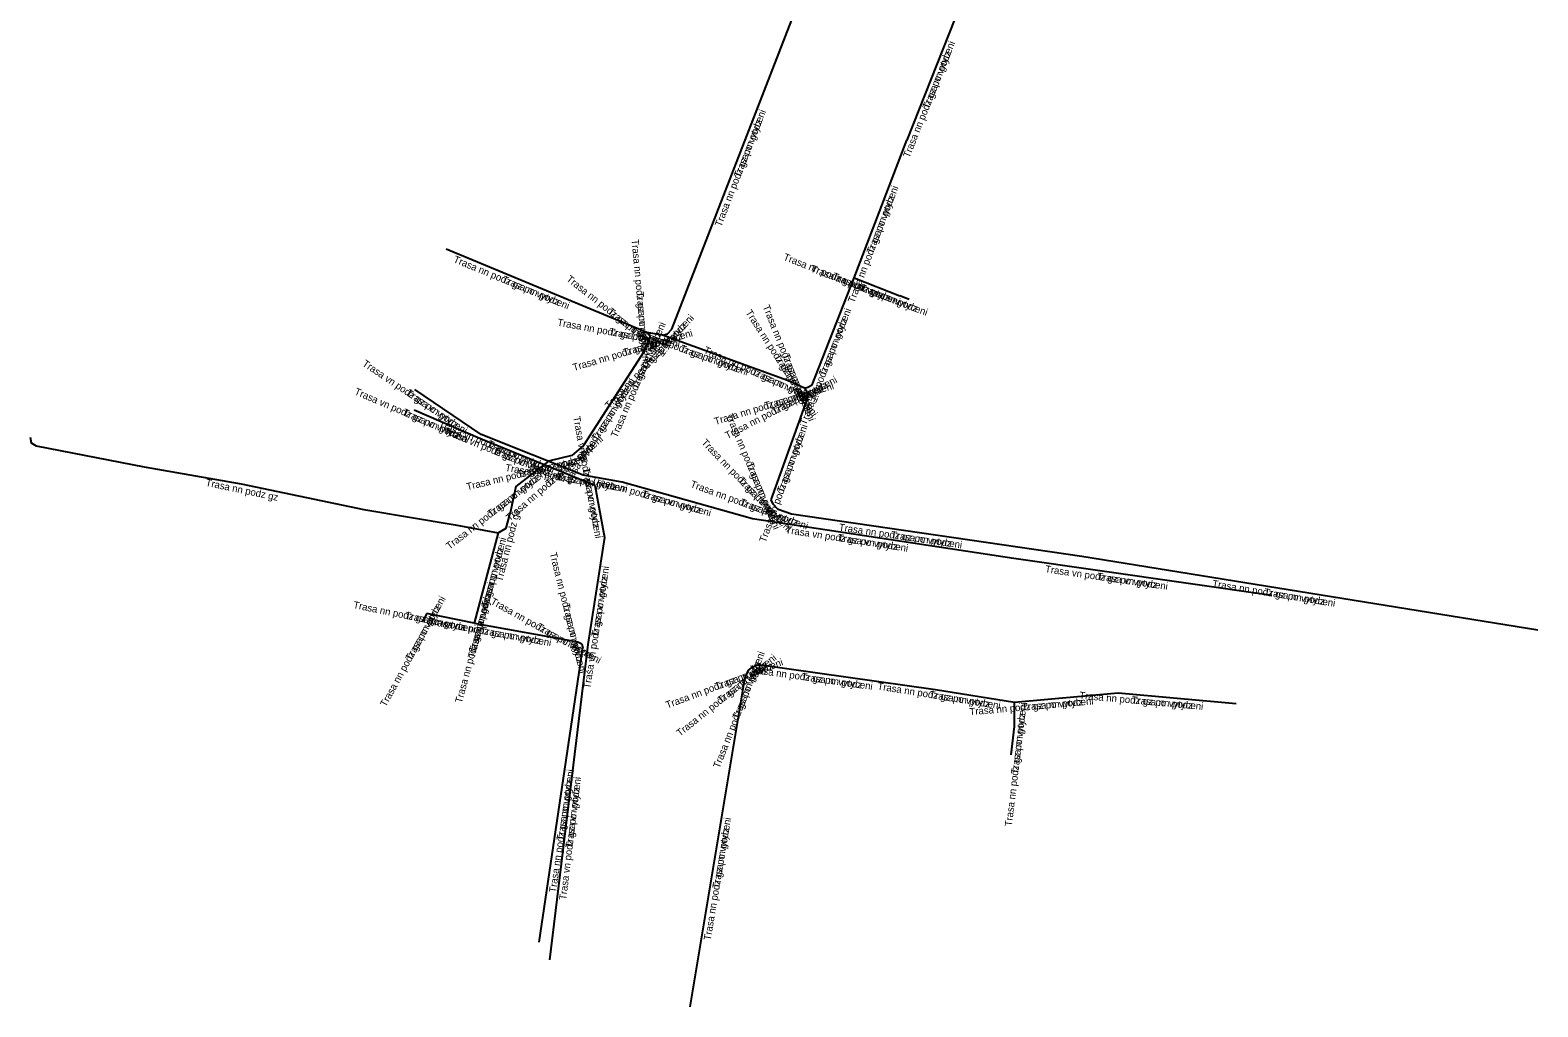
# Model space of a CAD drawing. Extents: x -644332 to -644190, y -1042435 to -1042173.
# Drawn here: x -644332.1 to -644226.7, y -1042434.8 to -1042366.5 of the extents above; entities that cross this region are included whole.
import ezdxf

# ---------------------------------------------------------------- set-up
doc = ezdxf.new("R2010")
doc.units = 0
for name, color, linetype in [('Popiskový text - Ostatní atributy Trasy', 7, 'Continuous'), ('Spojnice NN', 7, 'Continuous'), ('Spojnice VN', 7, 'Continuous')]:
    doc.layers.add(name, color=color, linetype=linetype)

msp = doc.modelspace()

# ---------------------------------------------------------------- linework, layer by layer
at = {"layer": 'Spojnice NN'}
for points in [[(-644287.28, -1042387.44), (-644276.63, -1042359.96)], [(-644287.28, -1042387.44), (-644276.63, -1042359.96)], [(-644266.64, -1042363.59), (-644270.85, -1042374.21)], [(-644266.64, -1042363.59), (-644270.85, -1042374.21)], [(-644274.53, -1042383.84), (-644270.85, -1042374.21)], [(-644274.53, -1042383.84), (-644270.85, -1042374.21)], [(-644289.02, -1042387.66), (-644303.05, -1042381.84)], [(-644289.02, -1042387.66), (-644303.05, -1042381.84)], [(-644277.47, -1042391.33), (-644274.53, -1042383.84)], [(-644277.47, -1042391.33), (-644274.53, -1042383.84)], [(-644274.53, -1042383.84), (-644271.32, -1042385.11)], [(-644274.53, -1042383.84), (-644271.32, -1042385.11)], [(-644270.67, -1042385.36), (-644271.32, -1042385.11)], [(-644270.67, -1042385.36), (-644271.32, -1042385.11)], [(-644287.92, -1042387.86), (-644289.02, -1042387.66)], [(-644289.02, -1042387.66), (-644288.83, -1042387.81)], [(-644287.92, -1042387.86), (-644289.02, -1042387.66)], [(-644289.02, -1042387.66), (-644288.83, -1042387.81)], [(-644287.58, -1042387.76), (-644287.28, -1042387.44)], [(-644287.58, -1042387.76), (-644287.28, -1042387.44)], [(-644289.23, -1042389.01), (-644288.81, -1042388.03)], [(-644289.23, -1042389.01), (-644288.81, -1042388.03)], [(-644288.83, -1042387.81), (-644288.81, -1042388.03)], [(-644288.83, -1042387.81), (-644288.81, -1042388.03)], [(-644287.92, -1042387.86), (-644287.58, -1042387.76)], [(-644287.92, -1042387.86), (-644287.58, -1042387.76)], [(-644279.19, -1042391.01), (-644287.92, -1042387.86)], [(-644279.19, -1042391.01), (-644287.92, -1042387.86)], [(-644289.23, -1042389.01), (-644293.46, -1042395.57)], [(-644289.23, -1042389.01), (-644293.46, -1042395.57)], [(-644277.99, -1042391.55), (-644279.19, -1042391.01)], [(-644277.99, -1042391.55), (-644279.19, -1042391.01)], [(-644277.99, -1042391.55), (-644277.76, -1042391.48)], [(-644277.99, -1042391.55), (-644277.76, -1042391.48)], [(-644277.83, -1042391.8), (-644277.99, -1042391.55)], [(-644277.83, -1042391.8), (-644277.99, -1042391.55)], [(-644277.71, -1042392.1), (-644277.83, -1042391.8)], [(-644277.71, -1042392.1), (-644277.83, -1042391.8)], [(-644277.76, -1042391.48), (-644277.47, -1042391.33)], [(-644277.76, -1042391.48), (-644277.47, -1042391.33)], [(-644280.32, -1042399.36), (-644277.71, -1042392.1)], [(-644280.32, -1042399.36), (-644277.71, -1042392.1)], [(-644332.14, -1042394.99), (-644332.07, -1042395.37), (-644331.72, -1042395.58), (-644324.16, -1042397.06), (-644317.38, -1042398.24), (-644308.82, -1042400.03), (-644302.43, -1042401.1), (-644299.41, -1042401.68)], [(-644293.46, -1042395.57), (-644294.27, -1042396.27)], [(-644293.46, -1042395.57), (-644294.27, -1042396.27)], [(-644295.89, -1042396.66), (-644298.17, -1042398.43), (-644298.61, -1042400.39)], [(-644295.89, -1042396.66), (-644298.17, -1042398.43), (-644298.61, -1042400.39)], [(-644294.27, -1042396.27), (-644295.89, -1042396.66)], [(-644294.27, -1042396.27), (-644295.89, -1042396.66)], [(-644280.19, -1042399.67), (-644280.32, -1042399.36)], [(-644280.19, -1042399.67), (-644280.32, -1042399.36)], [(-644279.84, -1042400.03), (-644280.19, -1042399.67)], [(-644279.84, -1042400.03), (-644280.19, -1042399.67)], [(-644278.91, -1042400.37), (-644279.84, -1042400.03)], [(-644278.91, -1042400.37), (-644279.84, -1042400.03)], [(-644299.41, -1042401.68), (-644298.85, -1042401.34), (-644298.61, -1042400.39)], [(-644258.61, -1042403.32), (-644278.91, -1042400.37)], [(-644258.61, -1042403.32), (-644278.91, -1042400.37)], [(-644299.41, -1042401.68), (-644300.48, -1042405.71)], [(-644299.41, -1042401.68), (-644300.48, -1042405.71)], [(-644226.72, -1042408.48), (-644258.61, -1042403.32)], [(-644226.72, -1042408.48), (-644258.61, -1042403.32)], [(-644300.48, -1042405.71), (-644301.1, -1042407.99)], [(-644300.48, -1042405.71), (-644301.1, -1042407.99)], [(-644304.4, -1042407.32), (-644304.69, -1042407.84)], [(-644304.4, -1042407.32), (-644304.69, -1042407.84)], [(-644301.1, -1042407.99), (-644304.4, -1042407.32)], [(-644301.1, -1042407.99), (-644304.4, -1042407.32)], [(-644301.1, -1042407.99), (-644293.84, -1042409.28)], [(-644301.1, -1042407.99), (-644293.84, -1042409.28)], [(-644296.55, -1042430.28), (-644293.5, -1042409.71)], [(-644296.55, -1042430.28), (-644293.5, -1042409.71)], [(-644293.84, -1042409.28), (-644293.57, -1042409.43)], [(-644293.84, -1042409.28), (-644293.57, -1042409.43)], [(-644293.57, -1042409.43), (-644293.5, -1042409.71)], [(-644293.57, -1042409.43), (-644293.5, -1042409.71)], [(-644281.62, -1042411.03), (-644281.22, -1042410.88)], [(-644281.62, -1042411.03), (-644281.22, -1042410.88)], [(-644281.22, -1042410.88), (-644268.83, -1042412.62)], [(-644281.22, -1042410.88), (-644268.83, -1042412.62)], [(-644285.99, -1042434.81), (-644282.16, -1042411.88)], [(-644285.99, -1042434.81), (-644282.16, -1042411.88)], [(-644282.16, -1042411.88), (-644281.92, -1042411.27)], [(-644282.16, -1042411.88), (-644281.92, -1042411.27)], [(-644281.92, -1042411.27), (-644281.62, -1042411.03)], [(-644281.92, -1042411.27), (-644281.62, -1042411.03)], [(-644268.83, -1042412.62), (-644263.32, -1042413.5)], [(-644268.83, -1042412.62), (-644263.32, -1042413.5)], [(-644263.32, -1042413.5), (-644256.06, -1042412.86)], [(-644263.32, -1042413.5), (-644256.06, -1042412.86)], [(-644256.06, -1042412.86), (-644247.81, -1042413.6)], [(-644256.06, -1042412.86), (-644247.81, -1042413.6)], [(-644263.55, -1042417.19), (-644263.31, -1042415.2), (-644263.32, -1042413.5)], [(-644263.55, -1042417.19), (-644263.31, -1042415.2), (-644263.32, -1042413.5)]]:
    msp.add_lwpolyline(points, dxfattribs=at)
at = {"layer": 'Spojnice VN'}
for points in [[(-644300.6, -1042394.79), (-644305.25, -1042391.66)], [(-644300.6, -1042394.79), (-644305.25, -1042391.66)], [(-644305.3, -1042393.08), (-644300.66, -1042395.08)], [(-644305.3, -1042393.08), (-644300.66, -1042395.08)], [(-644293.48, -1042397.64), (-644300.6, -1042394.79)], [(-644293.48, -1042397.64), (-644300.6, -1042394.79)], [(-644300.66, -1042395.08), (-644292.65, -1042398.34)], [(-644300.66, -1042395.08), (-644292.65, -1042398.34)], [(-644290.74, -1042398.12), (-644293.48, -1042397.64)], [(-644290.74, -1042398.12), (-644293.48, -1042397.64)], [(-644281.64, -1042400.68), (-644290.74, -1042398.12)], [(-644281.64, -1042400.68), (-644290.74, -1042398.12)], [(-644292.65, -1042398.34), (-644291.98, -1042402)], [(-644292.65, -1042398.34), (-644291.98, -1042402)], [(-644263.35, -1042403.46), (-644281.64, -1042400.68)], [(-644263.35, -1042403.46), (-644281.64, -1042400.68)], [(-644291.98, -1042402), (-644293.15, -1042409.48)], [(-644291.98, -1042402), (-644293.15, -1042409.48)], [(-644245.33, -1042406.04), (-644263.35, -1042403.46)], [(-644245.33, -1042406.04), (-644263.35, -1042403.46)], [(-644293.15, -1042409.48), (-644295.82, -1042431.52)], [(-644293.15, -1042409.48), (-644295.82, -1042431.52)]]:
    msp.add_lwpolyline(points, dxfattribs=at)

# ---------------------------------------------------------------- texts
at = {"layer": 'Popiskový text - Ostatní atributy Trasy'}
for s, rotation, p in [('Trasa nn podz gz po vytyceni', 68.3755, (-644270.66, -1042375.49)), ('Trasa nn podz', 68.3755, (-644269.3, -1042372.07)), ('Trasa nn podz gz po vytyceni', 68.8159, (-644283.82, -1042380.31)), ('Trasa nn podz', 68.8159, (-644282.49, -1042376.87)), ('Trasa nn podz gz po vytyceni', 69.0862, (-644274.52, -1042385.64)), ('Trasa nn podz', 69.0862, (-644273.21, -1042382.2)), ('Trasa nn podz gz po vytyceni', 275.1944, (-644290.09, -1042381.17)), ('Trasa nn podz gz po vytyceni', 337.4701, (-644302.59, -1042382.73)), ('Trasa nn podz gz po vytyceni', 338.4143, (-644279.52, -1042382.57)), ('Trasa nn podz gz po vytyceni', 338.992, (-644277.61, -1042383.39)), ('Trasa nn podz', 338.4143, (-644276.09, -1042383.92)), ('Trasa nn podz', 337.4701, (-644299.19, -1042384.14)), ('Trasa nn podz gz po vytyceni', 321.7098, (-644294.69, -1042384.01)), ('Trasa nn podz', 338.992, (-644274.17, -1042384.71)), ('Trasa nn podz', 275.1944, (-644289.75, -1042384.84)), ('Trasa nn podz gz po vytyceni', 46.8476, (-644291.63, -1042393.03)), ('Trasa nn podz', 321.7098, (-644291.8, -1042386.29)), ('Trasa nn podz gz po vytyceni', 302.6192, (-644282.14, -1042386.27)), ('Trasa nn podz gz po vytyceni', 291.9339, (-644280.93, -1042385.85)), ('Trasa nn podz gz po vytyceni', 68.5688, (-644277.89, -1042394.18)), ('Trasa nn podz gz po vytyceni', 349.6952, (-644295.31, -1042387.18)), ('Trasa nn podz gz po vytyceni', 16.3895, (-644294.12, -1042390.36)), ('Trasa nn podz', 349.6952, (-644291.68, -1042387.84)), ('Trasa nn podz gz po vytyceni', 66.8014, (-644291.11, -1042395.06)), ('Trasa nn podz', 66.8014, (-644289.66, -1042391.67)), ('Trasa nn podz gz po vytyceni', 340.1593, (-644290.2, -1042387.73)), ('Trasa nn podz', 46.8476, (-644289.11, -1042390.34)), ('Trasa nn podz', 68.5688, (-644276.55, -1042390.75)), ('Trasa nn podz', 16.3895, (-644290.59, -1042389.32)), ('Trasa nn podz', 340.1593, (-644286.74, -1042388.98)), ('Trasa nn podz gz po vytyceni', 335.7723, (-644285.09, -1042389.07)), ('Trasa vn podz gz po vytyceni', 326.0548, (-644308.96, -1042389.95)), ('Trasa nn podz', 302.6192, (-644280.15, -1042389.37)), ('Trasa nn podz', 291.9339, (-644279.55, -1042389.27)), ('Trasa nn podz gz po vytyceni', 57.1854, (-644294.5, -1042398.38)), ('Trasa nn podz gz po vytyceni', 27.3499, (-644283.39, -1042395.12)), ('Trasa nn podz', 335.7723, (-644281.73, -1042390.58)), ('Trasa vn podz gz po vytyceni', 336.6823, (-644309.51, -1042391.97)), ('Trasa vn podz', 326.0548, (-644305.9, -1042392.01)), ('Trasa nn podz', 57.1854, (-644292.5, -1042395.29)), ('Trasa nn podz gz po vytyceni', 16.9275, (-644284.22, -1042394.13)), ('Trasa nn podz', 16.9275, (-644280.7, -1042393.05)), ('Trasa nn podz', 27.3499, (-644280.11, -1042393.43)), ('Trasa vn podz', 336.6823, (-644306.13, -1042393.43)), ('Trasa vn podz gz po vytyceni', 338.1847, (-644303.63, -1042394.28)), ('Trasa vn podz gz po vytyceni', 280.3737, (-644294.18, -1042393.57)), ('Trasa nn podz gz po vytyceni', 292.751, (-644283.5, -1042393.47)), ('Trasa vn podz gz po vytyceni', 337.8541, (-644303.23, -1042394.74)), ('Trasa nn podz gz po vytyceni', 40.8335, (-644298.61, -1042400.88)), ('Trasa nn podz gz po vytyceni', 314.1931, (-644285.24, -1042395.4)), ('Trasa nn podz gz po vytyceni', 70.2313, (-644280.71, -1042402.38)), ('Trasa nn podz', 70.2313, (-644279.47, -1042398.91)), ('Trasa vn podz', 338.1847, (-644300.2, -1042395.65)), ('Trasa vn podz', 337.8541, (-644299.82, -1042396.13)), ('Trasa nn podz', 40.8335, (-644295.82, -1042398.47)), ('Trasa nn podz gz po vytyceni', 37.8228, (-644302.82, -1042402.86)), ('Trasa nn podz gz po vytyceni', 13.5359, (-644301.57, -1042398.7)), ('Trasa vn podz gz po vytyceni', 350.0636, (-644298.95, -1042397.34)), ('Trasa nn podz', 13.5359, (-644297.99, -1042397.83)), ('Trasa vn podz', 280.3737, (-644293.52, -1042397.19)), ('Trasa nn podz', 292.751, (-644282.07, -1042396.86)), ('Trasa nn podz gz', 348.189, (-644319.9, -1042398.38)), ('Trasa nn podz', 37.8228, (-644299.91, -1042400.6)), ('Trasa vn podz', 350.0636, (-644295.32, -1042397.98)), ('Trasa vn podz gz po vytyceni', 344.2877, (-644292.94, -1042398.18)), ('Trasa nn podz gz po vytyceni', 339.918, (-644286.02, -1042398.46)), ('Trasa nn podz', 314.1931, (-644282.68, -1042398.05)), ('Trasa vn podz', 344.2877, (-644289.4, -1042399.17)), ('Trasa nn podz', 339.918, (-644282.55, -1042399.73)), ('Trasa nn podz gz', 75.8219, (-644299.13, -1042405.12)), ('Trasa vn podz gz po vytyceni', 351.3574, (-644279.35, -1042401.69)), ('Trasa nn podz gz po vytyceni', 351.7316, (-644275.62, -1042401.51)), ('Trasa nn podz gz po vytyceni', 75.1305, (-644301.07, -1042410.47)), ('Trasa vn podz', 351.3574, (-644275.7, -1042402.24)), ('Trasa nn podz', 351.7316, (-644271.97, -1042402.04)), ('Trasa nn podz', 75.1305, (-644300.12, -1042406.9)), ('Trasa nn podz gz po vytyceni', 284.0362, (-644295.82, -1042403.1)), ('Trasa vn podz gz po vytyceni', 81.11, (-644292.98, -1042412.59)), ('Trasa vn podz gz po vytyceni', 351.8521, (-644261.2, -1042404.43)), ('Trasa vn podz', 351.8521, (-644257.55, -1042404.95)), ('Trasa nn podz gz po vytyceni', 74.7874, (-644301.96, -1042413.61)), ('Trasa vn podz', 81.11, (-644292.41, -1042408.95)), ('Trasa nn podz gz po vytyceni', 350.8088, (-644249.51, -1042405.45)), ('Trasa nn podz', 350.8088, (-644245.88, -1042406.04)), ('Trasa nn podz gz po vytyceni', 348.5232, (-644309.58, -1042406.93)), ('Trasa nn podz gz po vytyceni', 61.1339, (-644307.27, -1042413.88)), ('Trasa nn podz', 74.7874, (-644300.99, -1042410.06)), ('Trasa nn podz gz po vytyceni', 330.9454, (-644299.99, -1042406.61)), ('Trasa nn podz', 284.0362, (-644294.93, -1042406.67)), ('Trasa nn podz', 61.1339, (-644305.49, -1042410.65)), ('Trasa nn podz', 348.5232, (-644305.96, -1042407.67)), ('Trasa nn podz gz po vytyceni', 349.9245, (-644304.31, -1042408.08)), ('Trasa nn podz', 349.9245, (-644300.68, -1042408.72)), ('Trasa nn podz', 330.9454, (-644296.77, -1042408.39)), ('Trasa nn podz gz po vytyceni', 20.556, (-644287.59, -1042413.96)), ('Trasa nn podz gz po vytyceni', 38.6598, (-644286.7, -1042415.93)), ('Trasa nn podz gz po vytyceni', 68.5232, (-644283.94, -1042418.17)), ('Trasa nn podz', 20.556, (-644284.14, -1042412.67)), ('Trasa nn podz', 38.6598, (-644283.82, -1042413.62)), ('Trasa nn podz', 68.5232, (-644282.59, -1042414.74)), ('Trasa nn podz gz po vytyceni', 352.0059, (-644281.88, -1042411.44)), ('Trasa nn podz', 352.0059, (-644278.23, -1042411.96)), ('Trasa nn podz gz po vytyceni', 350.9259, (-644272.92, -1042412.62)), ('Trasa nn podz', 350.9259, (-644269.29, -1042413.21)), ('Trasa nn podz gz po vytyceni', 354.8745, (-644258.8, -1042413.27)), ('Trasa nn podz gz po vytyceni', 5.0378, (-644266.44, -1042414.43)), ('Trasa nn podz gz po vytyceni', 83.1232, (-644263.5, -1042422.21)), ('Trasa nn podz', 5.0378, (-644262.77, -1042414.1)), ('Trasa nn podz', 354.8745, (-644255.13, -1042413.6)), ('Trasa nn podz', 83.1232, (-644263.06, -1042418.55)), ('Trasa nn podz gz po vytyceni', 81.566, (-644295.38, -1042426.85)), ('Trasa nn podz', 81.566, (-644294.84, -1042423.2)), ('Trasa vn podz gz po vytyceni', 83.0927, (-644294.66, -1042427.36)), ('Trasa vn podz', 83.0927, (-644294.22, -1042423.7)), ('Trasa nn podz gz po vytyceni', 80.5174, (-644284.56, -1042430.19)), ('Trasa nn podz', 80.5174, (-644283.95, -1042426.56))]:
    msp.add_text(s, height=0.5, rotation=rotation, dxfattribs=at).set_placement(p)

doc.saveas('drawing.dxf')
